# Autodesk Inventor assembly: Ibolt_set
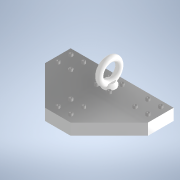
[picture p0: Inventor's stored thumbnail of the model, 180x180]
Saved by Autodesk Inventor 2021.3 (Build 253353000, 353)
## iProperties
Created: 2022-01
Part Number: Ibolt_set
Document SubType Name: Assembly
Designer: kengo
Author: kengo
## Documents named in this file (4)
- C:\Users\kengo\Documents\S2S_frame\SDC345\frame_misumi_ver7\Ibolt_set.iam
- C:\Users\kengo\Documents\S2S_frame\SDC345\frame_misumi_ver7\IboltPlate.ipt
- C:\Users\kengo\Documents\S2S_frame\SDC345\frame_misumi_ver7\CHI24.ipt
- C:\Users\kengo\Documents\S2S_frame\SDC345\frame_misumi_ver9\SCB8-50.ipt
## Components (18 placed, 3 different names)
1. IboltPlate:1 — リジッド:1, 回転:1, 回転:2, 回転:3, 回転:4, 回転:5, 回転:6, 回転:7, 回転:8, 回転:9, 回転:10, 回転:11, 回転:12, 回転:13, 回転:14, 回転:16, 回転:17
2. CHI24:1 — リジッド:1
3. SCB8-50:1 — 回転:2
4. SCB8-50:2 — 回転:1
5. SCB8-50:3 — 回転:4
6. SCB8-50:4 — 回転:3
7. SCB8-50:5 — 回転:6
8. SCB8-50:6 — 回転:8
9. SCB8-50:7 — 回転:5
10. SCB8-50:8 — 回転:7
11. SCB8-50:9 — 回転:12
12. SCB8-50:10 — 回転:9
13. SCB8-50:11 — 回転:10
14. SCB8-50:12 — 回転:11
15. SCB8-50:13 — 回転:17
16. SCB8-50:14 — 回転:16
17. SCB8-50:15 — 回転:13
18. SCB8-50:16 — 回転:14
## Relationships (17: RevoluteJoint 16, WeldJoint 1)
- リジッド:1 [WeldJoint]: IboltPlate:1 ↔ CHI24:1
- 回転:1 [RevoluteJoint]: IboltPlate:1 ↔ SCB8-50:2
- 回転:2 [RevoluteJoint]: IboltPlate:1 ↔ SCB8-50:1
- 回転:3 [RevoluteJoint]: IboltPlate:1 ↔ SCB8-50:4
- 回転:4 [RevoluteJoint]: IboltPlate:1 ↔ SCB8-50:3
- 回転:5 [RevoluteJoint]: IboltPlate:1 ↔ SCB8-50:7
- 回転:6 [RevoluteJoint]: IboltPlate:1 ↔ SCB8-50:5
- 回転:7 [RevoluteJoint]: IboltPlate:1 ↔ SCB8-50:8
- 回転:8 [RevoluteJoint]: IboltPlate:1 ↔ SCB8-50:6
- 回転:9 [RevoluteJoint]: IboltPlate:1 ↔ SCB8-50:10
- 回転:10 [RevoluteJoint]: IboltPlate:1 ↔ SCB8-50:11
- 回転:11 [RevoluteJoint]: IboltPlate:1 ↔ SCB8-50:12
- 回転:12 [RevoluteJoint]: IboltPlate:1 ↔ SCB8-50:9
- 回転:13 [RevoluteJoint]: IboltPlate:1 ↔ SCB8-50:15
- 回転:14 [RevoluteJoint]: IboltPlate:1 ↔ SCB8-50:16
- 回転:16 [RevoluteJoint]: IboltPlate:1 ↔ SCB8-50:14
- 回転:17 [RevoluteJoint]: IboltPlate:1 ↔ SCB8-50:13
